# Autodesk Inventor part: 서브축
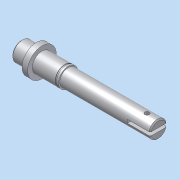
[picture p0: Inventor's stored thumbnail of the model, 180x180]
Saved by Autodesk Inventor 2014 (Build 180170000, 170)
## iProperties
Company: 한국ATC센터
Created: 2014-12
Part Number: 서브축
Document SubType Name: Modeling
Designer: KYOUNG IL JANG
Density: 1 g/cm^3
Mass: 23.2871 g
Surface Area: 76.512 cm^2
Volume: 23.2871 cm^3
Material: 일반
Appearance: 기본값
Author: KYOUNG IL JANG
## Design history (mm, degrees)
sketch "스케치1"
  geometry: L1 (0, 0)-(120, 0); L2 (0, 0)-(0, 7.5); L3 (1, 8.5)-(13, 8.5); L4 (13, 8.5)-(13, 12.5); L5 (13, 12.5)-(18, 12.5); L6 (18, 12.5)-(18, 8.5); L7 (18, 8.5)-(41, 8.5); L8 (120, 7.5)-(120, 0); L9 (0, 7.5)-(1, 8.5); L10 (41, 8.5)-(41, 7.5); L11 (41, 7.5)-(120, 7.5); 1 further point
  constraints: 22 end point, 3 parallel, 3 perpendicular, 2 collinear, 2 point on line, 2 vertical, 1 horizontal
  dimensions: "d0" = 5 distance of L4.end L5.end; "d1" = 17 diameter of L7 L1; "d2" = 13 distance of point (0, 8.5) L3.end; "d3" = 25 diameter of L5 L1; "d4" = 120 distance of L1.start L1.end; "d5" = 1 distance of L2.end point (0, 8.5); "d6" = 1 distance of L3.start point (0, 8.5) (= d5); "d15" = 15 diameter of L11 L1; "d16" = 23 distance of L6.end L7.end
revolve "회전1" sketch "스케치1" stored, may be unused: angle "d9" = 90 deg
node "작업 평면1"
sketch "스케치2"
  geometry: L1 (11.5, 12.5)-(11.5, -12.5) reference; L2 (-3, 2.5)-(6, 2.5); L3 (6, -2.5)-(-3, -2.5); A1 r 2.5 centre (6, 0) between (6, -2.5) and (6, 2.5); A2 r 2.5 centre (-3, 0) between (-3, 2.5) and (-3, -2.5); 1 further point
  constraints: 4 end point, 4 point on circle, 4 tangent, 2 centre point, 1 horizontal alignment, 1 parallel, 1 perpendicular
  dimensions: "d10" = 5 distance between parallel lines of L3 L2; "d11" = 14 dimension on A1 A2; "d12" = 3 distance edge to line of A1 L1
extrude "돌출1" cut sketch "스케치2" distance "d13" = 3; taper "d14" = 0 deg
sketch "스케치3"
  geometry: L1 (18, -12.5)-(18, 12.5) reference; L2 (13, -12.5)-(13, 12.5) reference; L3 (18, 8.5)-(41, 8.5) reference; L4 (38, 8.5)-(39.15, 8.5); L5 (39.15, 8.5)-(39.15, 8.1); L6 (39.15, 8.1)-(38, 8.1); L7 (38, 8.1)-(38, 8.5); L8 (-24, 0)-(144, 0) reference; 1 further point
  constraints: 8 end point, 2 parallel, 1 horizontal, 1 perpendicular, 1 point on line
  dimensions: "d17" = 20 distance between parallel lines of L7 L1; "d18" = 1.15 distance of L5.end L6.end; "d19" = 8.1 distance between parallel lines of L6 L8
revolve "회전2" sketch "스케치3" stored, may be unused: angle "d20" = 90 deg
chamfer "모따기1" distance "d21" = 1; stored, may be unused: second distance "d22" = 2, angle "d23" = 45 deg
sketch "스케치4"
  geometry: L1 (-120, 1.5)-(-100, 1.5); L2 (-100, 1.5)-(-100, -1.5); L3 (-100, -1.5)-(-120, -1.5); L4 (-120, -1.5)-(-120, 1.5); L5 (-120, -6.5)-(-120, 6.5) reference; 2 further points
  constraints: 8 end point, 2 parallel, 1 collinear, 1 horizontal, 1 horizontal alignment, 1 midpoint, 1 perpendicular
  dimensions: "d24" = 3 distance between parallel lines of L3 L1; "d25" = 20 distance of L2.end L3.end
extrude "돌출2" cut sketch "스케치4" stored distance "d26" = 10; taper "d27" = 0 deg
sketch "스케치5"
  geometry: L1 (120, 6.325)-(120, -6.325) reference; C1 r 2 at (110, 0); 1 further point
  constraints: 1 centre point, 1 horizontal alignment
  dimensions: "d28" = 4 diameter of C1; "d29" = 10 distance from line of L1 C1.centre
extrude "돌출3" cut sketch "스케치5" stored distance "d30" = 10; taper "d31" = 0 deg
node "솔리드1"
node "투영된 루프1"
